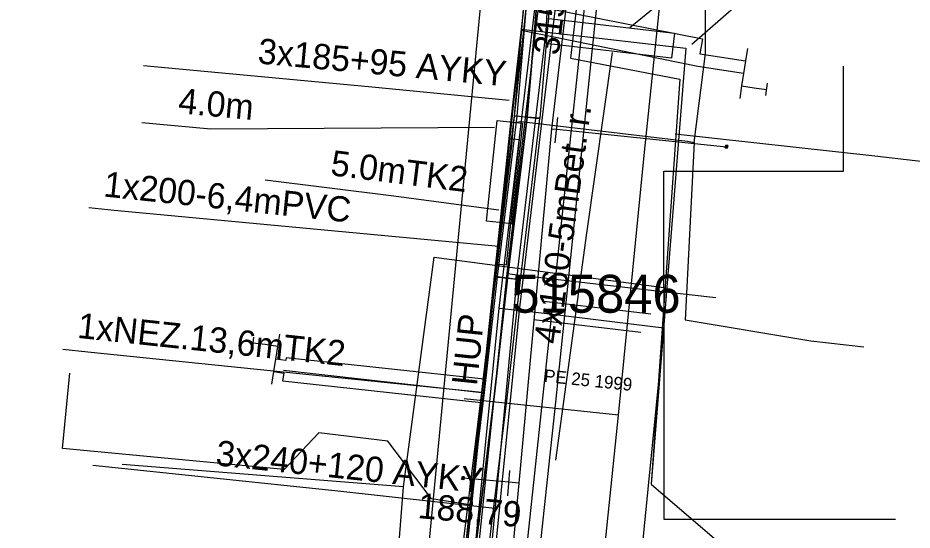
# Model space of a CAD drawing. Extents: x -746464 to -745690, y -1051581 to -1049993.
# Drawn here: x -746142.2 to -746106.85, y -1050812.22 to -1050791.97 of the extents above; entities that cross this region are included whole.
import ezdxf

# ---------------------------------------------------------------- set-up
doc = ezdxf.new("R2010")
doc.units = 0
for name, color, linetype in [('04_CETIN_neprovozovane', 7, 'Continuous'), ('04_CETIN_sdelovaci_podzem', 7, 'Continuous'), ('37_TVNET_sdelovaci_televizni kabely', 7, 'Continuous'), ('45_Eltodo_chranicka', 7, 'Continuous'), ('45_Eltodo_napajeci_kabel_NN', 7, 'Continuous'), ('45_Eltodo_popisy', 7, 'Continuous'), ('45_Eltodo_vedeni_NN_zemni', 7, 'Continuous'), ('48_Prazs_plynarenska_STL', 7, 'Continuous'), ('48_Prazs_plynarenska_STL_popisy', 7, 'Continuous'), ('51_PVaK_kanal_jednotna_overena poloha_rad', 7, 'Continuous'), ('51_PVaK_kanal_negravitacni_overena poloha', 7, 'Continuous'), ('51_PVaK_kanal_popisy', 7, 'Continuous'), ('51_PVaK_vodovod_chranicky_objekty', 7, 'Continuous'), ('51_PVaK_vodovod_NEPROVOZUJE PVK_neoverene poloha', 7, 'Continuous'), ('55_PREdi_chranicky', 7, 'Continuous'), ('55_PREdi_NN', 7, 'Continuous'), ('55_PREdi_NN_popisy', 7, 'Continuous'), ('55_PREdi_NN_pripojovaci_misto', 7, 'Continuous'), ('55_PREdi_stavby_popisy', 7, 'Continuous'), ('55_PREdi_VN', 7, 'Continuous'), ('55_PREdi_ZRUSENE_elektro', 7, 'Continuous')]:
    doc.layers.add(name, color=color, linetype=linetype)

msp = doc.modelspace()

# ---------------------------------------------------------------- linework, layer by layer
at = {"layer": '04_CETIN_neprovozovane'}
for points in [[(-746122.86, -1050802.08), (-746120.21, -1050779.57), (-746117.76, -1050758.96), (-746115.41, -1050737.5), (-746111.78, -1050719.1), (-746081.26, -1050611.75), (-746077.75, -1050600.04)], [(-746129.35, -1050866.18), (-746125.37, -1050826.31), (-746122.86, -1050802.08)], [(-746122.86, -1050802.08), (-746122.56, -1050802.12), (-746116.6, -1050802.8), (-746114.61, -1050803.03)]]:
    msp.add_lwpolyline(points, dxfattribs=at)
at = {"layer": '04_CETIN_sdelovaci_podzem'}
for points in [[(-746122.59, -1050796.1), (-746121.03, -1050781.62)], [(-746115.46, -1050796.89), (-746115.02, -1050793.37), (-746115, -1050789.9), (-746115.81, -1050789.22), (-746115.25, -1050782.33), (-746113.94, -1050782.35), (-746113.68, -1050782.38), (-746112.96, -1050782.46)], [(-746122.59, -1050796.1), (-746122.3, -1050796.07), (-746115.73, -1050796.84), (-746115.46, -1050796.89)], [(-746122.3, -1050796.07), (-746115.73, -1050796.84)], [(-746124.26, -1050811.23), (-746123.4, -1050803.03), (-746122.67, -1050797.02), (-746122.59, -1050796.1)], [(-746123.4, -1050803.03), (-746122.67, -1050797.02)], [(-746115.46, -1050796.89), (-746115.82, -1050803.91), (-746110.85, -1050804.74), (-746108.76, -1050804.98)], [(-746122.56, -1050802.12), (-746116.6, -1050802.8)], [(-746124.26, -1050811.23), (-746125.85, -1050810.98), (-746127.58, -1050808.7), (-746130.3, -1050808.37), (-746131.67, -1050809.83), (-746140.44, -1050809), (-746140.15, -1050806.02)], [(-746127.41, -1050839.9), (-746126.38, -1050831.01), (-746125.72, -1050824.91), (-746124.26, -1050811.23)]]:
    msp.add_lwpolyline(points, dxfattribs=at)
at = {"layer": '37_TVNET_sdelovaci_televizni kabely'}
for points in [[(-745984.595, -1050626.363), (-746079.15, -1050602.616), (-746117.902, -1050728.62), (-746140.499, -1050964.785), (-746150.343, -1051014.385), (-746134.374, -1051025.766), (-746053.56, -1051028.358)], [(-746116.665, -1050802.626), (-746116.665, -1050798.03), (-746109.56, -1050798.03), (-746109.56, -1050793.872)], [(-746126.951, -1050810.506), (-746125.747, -1050801.423), (-746116.665, -1050802.626), (-746116.669, -1050811.788), (-746107.507, -1050811.793)], [(-746129.029, -1050836.879), (-746126.951, -1050810.506), (-746138.072, -1050809.629)]]:
    msp.add_lwpolyline(points, dxfattribs=at)
at = {"layer": '45_Eltodo_chranicka'}
for points in [[(-746117.174, -1050803.684), (-746121.401, -1050803.186)], [(-746117.571, -1050804.411), (-746121.798, -1050803.913)]]:
    msp.add_lwpolyline(points, dxfattribs=at)
at = {"layer": '45_Eltodo_napajeci_kabel_NN'}
msp.add_lwpolyline([(-746165.45, -1051019.12), (-746165.712, -1051018.023), (-746163.467, -1051013.836), (-746155.197, -1051018.912), (-746150.32, -1051019.043), (-746148.604, -1051010.158), (-746143.982, -1050988.385), (-746139.729, -1050968.164), (-746137.496, -1050944.441), (-746135.374, -1050923.74), (-746132.775, -1050899.638), (-746130.229, -1050876.488), (-746127.576, -1050852.278), (-746125.136, -1050831.143), (-746122.376, -1050803.534), (-746119.744, -1050781.489), (-746120.222, -1050780.456), (-746117.893, -1050761.331)], dxfattribs=at)
at = {"layer": '45_Eltodo_vedeni_NN_zemni'}
for points in [[(-746123.171, -1050803.447), (-746120.625, -1050782.102)], [(-746125.931, -1050831.057), (-746123.171, -1050803.447)], [(-746123.171, -1050803.447), (-746121.726, -1050803.607), (-746116.667, -1050804.218), (-746117.934, -1050816.978), (-746109.511, -1050817.921)]]:
    msp.add_lwpolyline(points, dxfattribs=at)
at = {"layer": '48_Prazs_plynarenska_STL'}
for points in [[(-746128.924, -1050901.967), (-746128.119, -1050893.674), (-746126.8, -1050880.15), (-746126.425, -1050876.727), (-746123.398, -1050849.062), (-746122.397, -1050839.917), (-746121.85, -1050834.92), (-746119.64, -1050819.16), (-746118.456, -1050807.673), (-746117.44, -1050797.41), (-746116.892, -1050792.088), (-746116.554, -1050788.806), (-746115.818, -1050781.644), (-746115.679, -1050780.281), (-746115.164, -1050775.276), (-746114.581, -1050769.606)], [(-746118.456, -1050807.673), (-746124.555, -1050807.035)]]:
    msp.add_lwpolyline(points, dxfattribs=at)
at = {"layer": '51_PVaK_kanal_jednotna_overena poloha_rad'}
msp.add_lwpolyline([(-746122.06, -1050812.8), (-746118.336, -1050777.89), (-746116.83, -1050763.77)], dxfattribs=at)
at = {"layer": '51_PVaK_kanal_negravitacni_overena poloha'}
msp.add_lwpolyline([(-746115.12, -1050753.61), (-746115.37, -1050757.26), (-746117.04, -1050771.19), (-746118.85, -1050786.94), (-746120.95, -1050807.16), (-746122.42, -1050820.88)], dxfattribs=at)
at = {"layer": '51_PVaK_vodovod_chranicky_objekty'}
for p, q in [((-746120.955, -1050796.91), (-746120.854, -1050795.91)), ((-746114.239, -1050797.103), (-746114.13, -1050797.014)), ((-746114.239, -1050797.103), (-746114.237, -1050797.084)), ((-746114.239, -1050797.103), (-746114.219, -1050797.105)), ((-746114.229, -1050797.004), (-746114.231, -1050797.024)), ((-746114.229, -1050797.004), (-746114.14, -1050797.114)), ((-746114.229, -1050797.004), (-746114.209, -1050797.006)), ((-746114.14, -1050797.114), (-746114.16, -1050797.112)), ((-746114.13, -1050797.014), (-746114.149, -1050797.012)), ((-746114.14, -1050797.114), (-746114.138, -1050797.094)), ((-746114.13, -1050797.014), (-746114.132, -1050797.034)), ((-746122.836, -1050810.87), (-746122.75, -1050809.87)), ((-746124.659, -1050810.211), (-746124.551, -1050810.12)), ((-746124.659, -1050810.211), (-746124.658, -1050810.191)), ((-746124.659, -1050810.211), (-746124.64, -1050810.213)), ((-746124.651, -1050810.112), (-746124.652, -1050810.131)), ((-746124.651, -1050810.112), (-746124.56, -1050810.22)), ((-746124.651, -1050810.112), (-746124.631, -1050810.113)), ((-746124.56, -1050810.22), (-746124.58, -1050810.218)), ((-746124.551, -1050810.12), (-746124.571, -1050810.119)), ((-746124.56, -1050810.22), (-746124.558, -1050810.2)), ((-746124.551, -1050810.12), (-746124.553, -1050810.14))]:
    msp.add_line(p, q, dxfattribs=at)
for points in [[(-746114.135, -1050797.064), (-746114.134, -1050797.059), (-746114.135, -1050797.054), (-746114.135, -1050797.049), (-746114.137, -1050797.044), (-746114.139, -1050797.038), (-746114.142, -1050797.034), (-746114.144, -1050797.03), (-746114.148, -1050797.025), (-746114.151, -1050797.022), (-746114.155, -1050797.019), (-746114.16, -1050797.015), (-746114.165, -1050797.013), (-746114.169, -1050797.011), (-746114.174, -1050797.01), (-746114.179, -1050797.009), (-746114.184, -1050797.009), (-746114.189, -1050797.009), (-746114.194, -1050797.01), (-746114.2, -1050797.011), (-746114.205, -1050797.013), (-746114.209, -1050797.016), (-746114.213, -1050797.019), (-746114.218, -1050797.022), (-746114.221, -1050797.026), (-746114.225, -1050797.03), (-746114.228, -1050797.034), (-746114.231, -1050797.039), (-746114.232, -1050797.044), (-746114.234, -1050797.049), (-746114.234, -1050797.054), (-746114.235, -1050797.059), (-746114.234, -1050797.064), (-746114.234, -1050797.069), (-746114.232, -1050797.074), (-746114.23, -1050797.079), (-746114.227, -1050797.084), (-746114.225, -1050797.088), (-746114.221, -1050797.092), (-746114.217, -1050797.096), (-746114.214, -1050797.099), (-746114.209, -1050797.103), (-746114.204, -1050797.105), (-746114.199, -1050797.107), (-746114.194, -1050797.108), (-746114.19, -1050797.109), (-746114.185, -1050797.109), (-746114.179, -1050797.109), (-746114.174, -1050797.108), (-746114.169, -1050797.107), (-746114.164, -1050797.104), (-746114.16, -1050797.102), (-746114.155, -1050797.099), (-746114.151, -1050797.095), (-746114.148, -1050797.092), (-746114.144, -1050797.088), (-746114.141, -1050797.083), (-746114.138, -1050797.079), (-746114.137, -1050797.074), (-746114.135, -1050797.069), (-746114.135, -1050797.064)], [(-746124.555, -1050810.17), (-746124.555, -1050810.165), (-746124.556, -1050810.16), (-746124.556, -1050810.155), (-746124.558, -1050810.15), (-746124.56, -1050810.145), (-746124.563, -1050810.14), (-746124.565, -1050810.136), (-746124.569, -1050810.132), (-746124.573, -1050810.129), (-746124.576, -1050810.125), (-746124.581, -1050810.122), (-746124.586, -1050810.119), (-746124.591, -1050810.118), (-746124.596, -1050810.116), (-746124.601, -1050810.116), (-746124.606, -1050810.116), (-746124.611, -1050810.116), (-746124.616, -1050810.117), (-746124.621, -1050810.118), (-746124.626, -1050810.121), (-746124.631, -1050810.123), (-746124.635, -1050810.126), (-746124.639, -1050810.13), (-746124.642, -1050810.133), (-746124.646, -1050810.137), (-746124.649, -1050810.142), (-746124.652, -1050810.147), (-746124.653, -1050810.151), (-746124.655, -1050810.156), (-746124.655, -1050810.161), (-746124.655, -1050810.166), (-746124.655, -1050810.171), (-746124.654, -1050810.176), (-746124.653, -1050810.182), (-746124.65, -1050810.187), (-746124.648, -1050810.191), (-746124.645, -1050810.195), (-746124.641, -1050810.2), (-746124.638, -1050810.203), (-746124.634, -1050810.206), (-746124.629, -1050810.21), (-746124.624, -1050810.212), (-746124.62, -1050810.214), (-746124.615, -1050810.215), (-746124.61, -1050810.216), (-746124.605, -1050810.216), (-746124.6, -1050810.215), (-746124.595, -1050810.215), (-746124.589, -1050810.213), (-746124.584, -1050810.211), (-746124.58, -1050810.208), (-746124.576, -1050810.206), (-746124.571, -1050810.202), (-746124.568, -1050810.198), (-746124.565, -1050810.195), (-746124.561, -1050810.19), (-746124.559, -1050810.185), (-746124.557, -1050810.18), (-746124.556, -1050810.175), (-746124.555, -1050810.17)]]:
    msp.add_lwpolyline(points, dxfattribs=at)
at = {"layer": '51_PVaK_vodovod_NEPROVOZUJE PVK_neoverene poloha'}
for p, q in [((-746121.099, -1050796.35), (-746120.9, -1050796.37)), ((-746120.9, -1050796.37), (-746114.186, -1050797.06)), ((-746122.79, -1050810.33), (-746124.606, -1050810.167)), ((-746122.392, -1050810.364), (-746122.79, -1050810.33))]:
    msp.add_line(p, q, dxfattribs=at)
msp.add_lwpolyline([(-746119.36, -1050777.72), (-746119.951, -1050786.603), (-746121.099, -1050796.35), (-746122.392, -1050810.364), (-746123.931, -1050826.638), (-746127.054, -1050855.254), (-746129.164, -1050875.152), (-746130.599, -1050887.055)], dxfattribs=at)
at = {"layer": '55_PREdi_chranicky'}
for points in [[(-746120.49, -1050781.41), (-746119.994, -1050781.473), (-746121.043, -1050789.693), (-746121.572, -1050795.932), (-746122.07, -1050795.89), (-746122.568, -1050795.848), (-746122.037, -1050789.587), (-746120.986, -1050781.347), (-746120.49, -1050781.41)], [(-746121.331, -1050792.987), (-746121.215, -1050791.993), (-746116.248, -1050792.568), (-746116.364, -1050793.562), (-746121.331, -1050792.987)], [(-746123.251, -1050796.03), (-746122.256, -1050796.134), (-746122.678, -1050800.112), (-746123.673, -1050800.008), (-746123.251, -1050796.03)], [(-746122.07, -1050795.89), (-746121.574, -1050795.95), (-746122.344, -1050802.32), (-746122.84, -1050802.26), (-746123.336, -1050802.2), (-746122.566, -1050795.83), (-746122.07, -1050795.89)], [(-746122.783, -1050796.737), (-746122.385, -1050796.777), (-746122.893, -1050801.751), (-746123.291, -1050801.711), (-746122.783, -1050796.737)], [(-746122.84, -1050802.26), (-746122.343, -1050802.317), (-746122.863, -1050806.889), (-746123.954, -1050815.831), (-746124.45, -1050815.77), (-746124.946, -1050815.709), (-746123.857, -1050806.771), (-746123.337, -1050802.203), (-746122.84, -1050802.26)]]:
    msp.add_lwpolyline(points, close=True, dxfattribs=at)
at = {"layer": '55_PREdi_NN'}
for points in [[(-746079.707, -1050608.094), (-746081.337, -1050613.521), (-746088.598, -1050639.168), (-746100.883, -1050680.307), (-746109.804, -1050710.935), (-746113.542, -1050724.97), (-746114.797, -1050736.143), (-746116.957, -1050755.942), (-746121.273, -1050791.507), (-746121.329, -1050792.488), (-746122.44, -1050801.822), (-746124.772, -1050826.479), (-746132.514, -1050898.319), (-746135.263, -1050933.408), (-746137.115, -1050954.341), (-746141.612, -1050953.806)], [(-746131.053, -1050785.848), (-746131.175, -1050786.894), (-746130.928, -1050787.938), (-746121.896, -1050789.004), (-746122.205, -1050791.403), (-746115.141, -1050792.798), (-746115.241, -1050793.391), (-746113.437, -1050793.669)], [(-746121.791, -1050788.037), (-746121.849, -1050788.537), (-746122.298, -1050792.414)], [(-746119.869, -1050789.369), (-746120.347, -1050793.554), (-746116.03, -1050794.387), (-746117.167, -1050810.412), (-746109.962, -1050816.591), (-746089.48, -1050819.916)], [(-746113.513, -1050794.163), (-746115.317, -1050793.885), (-746122.307, -1050792.463), (-746123.768, -1050806.257), (-746131.593, -1050805.416), (-746131.61, -1050805.52), (-746132.002, -1050805.459)], [(-746122.298, -1050792.414), (-746122.713, -1050795.995), (-746123.857, -1050806.782)], [(-746122.298, -1050792.414), (-746115.792, -1050793.167)], [(-746115.792, -1050793.167), (-746117.167, -1050810.412), (-746109.962, -1050816.591), (-746089.464, -1050819.918), (-746086.466, -1050820.405), (-746058.148, -1050827.712), (-746044.831, -1050828.833)], [(-746113.361, -1050793.175), (-746113.437, -1050793.669), (-746113.513, -1050794.163), (-746113.589, -1050794.657), (-746113.665, -1050795.151)], [(-746113.589, -1050794.657), (-746113.095, -1050794.733)], [(-746132.155, -1050806.447), (-746132.078, -1050805.953), (-746132.002, -1050805.459), (-746131.925, -1050804.965), (-746131.848, -1050804.471)], [(-746131.925, -1050804.965), (-746132.419, -1050804.888)], [(-746132.078, -1050805.953), (-746131.686, -1050806.014), (-746131.733, -1050806.313), (-746123.88, -1050807.182), (-746125.767, -1050826.376), (-746125.983, -1050828.466), (-746133.921, -1050827.568), (-746133.975, -1050827.823), (-746134.456, -1050827.721)], [(-746131.704, -1050805.901), (-746123.857, -1050806.782)], [(-746123.857, -1050806.782), (-746124.643, -1050814.172), (-746125.764, -1050826.265), (-746126.054, -1050828.925)]]:
    msp.add_lwpolyline(points, dxfattribs=at)
at = {"layer": '55_PREdi_NN_popisy'}
for points in [[(-746115.556, -1050793.008), (-746109.368, -1050787.592), (-746108.465, -1050778.701)], [(-746118.012, -1050792.349), (-746112.413, -1050787.766), (-746111.426, -1050778.884)], [(-746137.239, -1050793.854), (-746128.341, -1050794.675), (-746122.783, -1050795.222)], [(-746116.221, -1050796.556), (-746108.315, -1050797.427), (-746098.755, -1050798.523)], [(-746139.243, -1050809.654), (-746129.673, -1050810.657), (-746123.342, -1050811.356)]]:
    msp.add_lwpolyline(points, dxfattribs=at)
at = {"layer": '55_PREdi_NN_pripojovaci_misto'}
for p, q in [((-746112.629, -1050795.042), (-746112.568, -1050794.546)), ((-746113.095, -1050794.733), (-746112.599, -1050794.794)), ((-746132.89, -1050804.587), (-746132.942, -1050805.084)), ((-746132.419, -1050804.888), (-746132.916, -1050804.836))]:
    msp.add_line(p, q, dxfattribs=at)
at = {"layer": '55_PREdi_stavby_popisy'}
for points in [[(-746120.927, -1050809.454), (-746119.705, -1050800.478), (-746118.698, -1050793.335)], [(-746137.3, -1050796.106), (-746134.567, -1050796.358), (-746123.357, -1050796.29)], [(-746132.418, -1050798.371), (-746127.447, -1050798.992), (-746123.18, -1050799.561)], [(-746139.393, -1050799.47), (-746138.398, -1050799.576), (-746123.189, -1050800.999)], [(-746140.425, -1050805.061), (-746139.43, -1050805.167), (-746123.857, -1050806.771)]]:
    msp.add_lwpolyline(points, dxfattribs=at)
at = {"layer": '55_PREdi_VN'}
for points in [[(-746131.88, -1050884.63), (-746131.62, -1050883.43), (-746131.05, -1050877.84), (-746130.27, -1050870.78), (-746129.47, -1050863.79), (-746128.9, -1050858.11), (-746128.23, -1050852.6), (-746127.82, -1050848.89), (-746126.8, -1050839.19), (-746125.42, -1050825.95), (-746124.45, -1050815.77), (-746123.36, -1050806.83), (-746122.84, -1050802.26), (-746122.07, -1050795.89), (-746121.54, -1050789.64), (-746120.49, -1050781.41), (-746119.82, -1050775.83), (-746119.1, -1050768.57)], [(-746119.1, -1050768.57), (-746119.82, -1050775.83), (-746120.49, -1050781.41), (-746121.54, -1050789.64), (-746122.07, -1050795.89), (-746122.84, -1050802.26), (-746123.36, -1050806.83), (-746124.45, -1050815.77), (-746125.42, -1050825.95), (-746126.8, -1050839.19), (-746127.82, -1050848.89), (-746128.23, -1050852.6), (-746128.9, -1050858.11), (-746129.337, -1050862.469), (-746129.47, -1050863.79), (-746130.27, -1050870.78), (-746131.05, -1050877.84), (-746131.62, -1050883.43), (-746131.88, -1050884.63)]]:
    msp.add_lwpolyline(points, dxfattribs=at)
at = {"layer": '55_PREdi_ZRUSENE_elektro'}
msp.add_lwpolyline([(-746129.741, -1050862.453), (-746129.298, -1050858.066), (-746128.627, -1050852.554), (-746128.218, -1050848.847), (-746127.198, -1050839.148), (-746125.818, -1050825.91), (-746124.848, -1050815.727), (-746123.757, -1050806.783), (-746123.237, -1050802.213), (-746122.468, -1050795.849), (-746121.938, -1050789.598), (-746120.887, -1050781.361), (-746120.218, -1050775.786), (-746119.498, -1050768.529)], dxfattribs=at)

# ---------------------------------------------------------------- texts
at = {"layer": '45_Eltodo_popisy'}
msp.add_text('515846', height=1.5, dxfattribs=at).set_placement((-746122.691, -1050803.627))
at = {"layer": '48_Prazs_plynarenska_STL_popisy'}
for s, height, rotation, p in [('HUP', 1, 84, (-746124.055, -1050806.535)), ('PE 25 1999', 0.5, 354.0282, (-746121.417, -1050806.358))]:
    msp.add_text(s, height=height, rotation=rotation, dxfattribs=at).set_placement(p)
at = {"layer": '51_PVaK_kanal_popisy'}
for s, rotation, p in [('315PVC', 82.9111, (-746120.822, -1050793.471)), ('188,79', 354.9073, (-746126.416, -1050811.744))]:
    msp.add_text(s, height=1, rotation=rotation, dxfattribs=at).set_placement(p)
at = {"layer": '55_PREdi_NN_popisy'}
for s, rotation, p in [('3x185+95 AYKY', 354.7288, (-746132.744, -1050793.766)), ('3x240+120 AYKY', 354.0131, (-746134.406, -1050809.659))]:
    msp.add_text(s, height=1, rotation=rotation, dxfattribs=at).set_placement(p)
at = {"layer": '55_PREdi_stavby_popisy'}
for s, rotation, p in [('4.0m', 354.7273, (-746135.887, -1050795.734)), ('4x160-5mBet. r.', 82.2476, (-746120.811, -1050804.899)), ('5.0mTK2', 352.8704, (-746129.87, -1050798.186)), ('1x200-6,4mPVC', 353.9366, (-746138.843, -1050799.026)), ('1xNEZ.13,6mTK2', 353.9441, (-746139.874, -1050804.617))]:
    msp.add_text(s, height=1, rotation=rotation, dxfattribs=at).set_placement(p)

doc.saveas('drawing.dxf')
